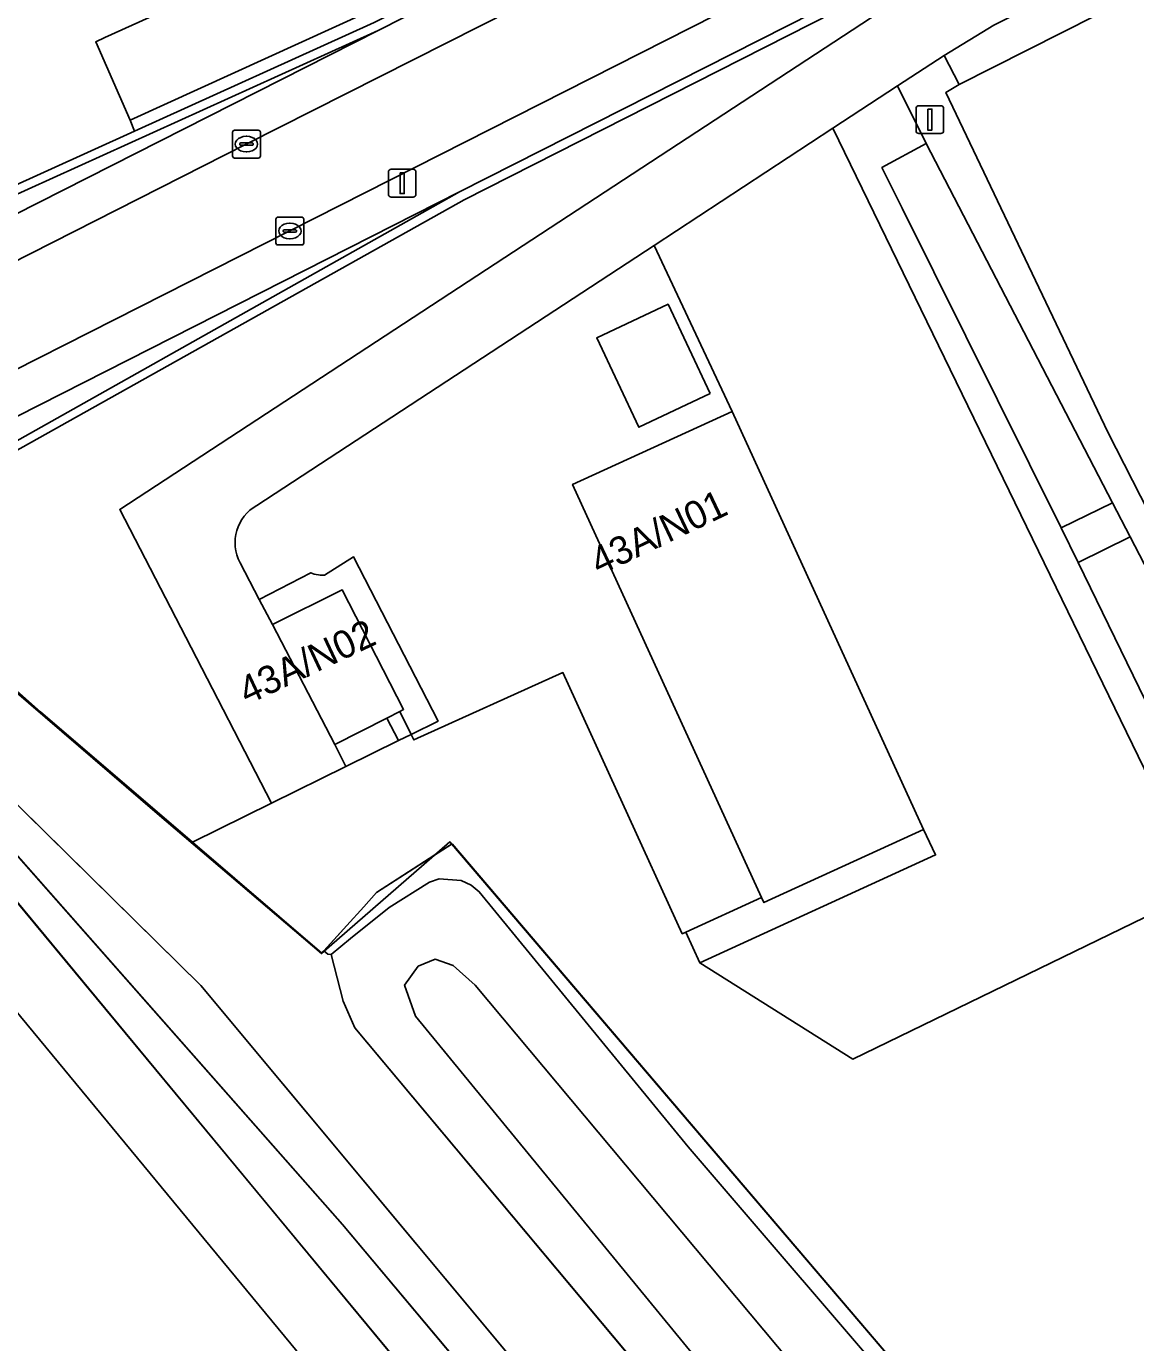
# Model space of a CAD drawing. Extents: x 157320 to 158835, y 386650 to 388491.
# Drawn here: x 157425.92 to 157465.77, y 387529.81 to 387577.08 of the extents above; entities that cross this region are included whole.
import ezdxf

# ---------------------------------------------------------------- set-up
doc = ezdxf.new("R2010")
doc.units = 0
for name, color, linetype in [('IMGEO_Berm_open', 7, 'Continuous'), ('IMGEO_Dek', 7, 'Continuous'), ('IMGEO_Erf', 7, 'Continuous'), ('IMGEO_Fietspad_gesloten', 7, 'Continuous'), ('IMGEO_Geluidsscherm', 7, 'Continuous'), ('IMGEO_Grasland_overig', 7, 'Continuous'), ('IMGEO_Groenvoorziening', 7, 'Continuous'), ('IMGEO_Hek', 7, 'Continuous'), ('IMGEO_Kolk', 7, 'Continuous'), ('IMGEO_Lichtmast', 7, 'Continuous'), ('IMGEO_Meer_plas_ven_vijver', 7, 'Continuous'), ('IMGEO_Muur', 7, 'Continuous'), ('IMGEO_Oever', 7, 'Continuous'), ('IMGEO_Pand', 7, 'Continuous'), ('IMGEO_Pand_nummerreeks', 7, 'Continuous'), ('IMGEO_Parkeervlak_open', 7, 'Continuous'), ('IMGEO_Rijbaan_lokaal_open', 7, 'Continuous'), ('IMGEO_Spoor', 7, 'Continuous'), ('IMGEO_Spoorbaan_halfverhard', 7, 'Continuous'), ('IMGEO_Voetpad_open', 7, 'Continuous'), ('IMGEO_Waterloop', 7, 'Continuous')]:
    doc.layers.add(name, color=color, linetype=linetype)

msp = doc.modelspace()

# ---------------------------------------------------------------- linework, layer by layer
at = {"layer": 'IMGEO_Berm_open'}
for points in [[(157470.771, 387593.59), (157470.568, 387593.961), (157468.366, 387592.876), (157467.91, 387592.639), (157452.596, 387584.902), (157438.44, 387577.734), (157438.25, 387577.629), (157429.654, 387573.707), (157429.806, 387573.314), (157438.415, 387577.215)], [(157438.555, 387576.929), (157414.303, 387565.939), (157415.05, 387565.021)], [(157441.48, 387571.141), (157419.244, 387559.866), (157419.925, 387559.029)]]:
    msp.add_lwpolyline(points, close=True, dxfattribs=at)
at = {"layer": 'IMGEO_Dek'}
msp.add_lwpolyline([(157463.092, 387559.076), (157463.702, 387557.826), (157465.573, 387558.748), (157464.941, 387559.968)], close=True, dxfattribs=at)
at = {"layer": 'IMGEO_Erf'}
for points in [[(157414.095, 387566.194), (157429.806, 387573.314), (157429.654, 387573.707), (157428.415, 387576.527), (157428.741, 387576.675), (157434.392, 387579.243), (157433.897, 387580.178), (157436.414, 387581.319), (157439.973, 387583.126), (157444.069, 387585.194), (157444.6, 387585.462), (157468.188, 387597.53), (157456.697, 387614.284)], [(157445.197, 387553.877), (157449.484, 387544.495), (157449.612, 387544.553), (157452.333, 387545.796), (157445.544, 387560.633), (157451.273, 387563.255), (157448.47, 387569.217), (157434.202, 387559.877)], [(157433.601, 387557.819), (157434.292, 387556.505), (157436.148, 387557.459), (157436.265, 387557.415), (157436.488, 387557.372), (157436.637, 387557.369), (157437.678, 387558.031), (157440.715, 387552.135), (157439.747, 387551.657), (157439.845, 387551.46), (157445.197, 387553.877)]]:
    msp.add_lwpolyline(points, dxfattribs=at)
for points in [[(157489.504, 387580.154), (157485.892, 387588.103), (157485.789, 387588.051), (157485.69, 387588.242), (157478.875, 387584.813), (157476.738, 387583.733), (157476.239, 387583.497), (157475.415, 387583.071), (157459.432, 387574.995), (157458.953, 387574.71), (157464.773, 387562.506), (157473.594, 387545.224), (157492.088, 387553.929), (157499.149, 387557.253), (157498.521, 387559.147)], [(157450.489, 387563.891), (157447.928, 387562.682), (157446.413, 387565.891), (157448.973, 387567.1)]]:
    msp.add_lwpolyline(points, close=True, dxfattribs=at)
msp.add_arc((157434.947, 387558.543), 1.528, 119.1728, 208.2683, dxfattribs=at)
at = {"layer": 'IMGEO_Fietspad_gesloten'}
msp.add_lwpolyline([(157418.265, 387561.069), (157435.385, 387569.732), (157456.986, 387580.686), (157473.14, 387588.869), (157472.349, 387590.404), (157471.557, 387591.939), (157455.422, 387583.768), (157433.825, 387572.851), (157416.027, 387563.82)], close=True, dxfattribs=at)
at = {"layer": 'IMGEO_Geluidsscherm'}
msp.add_lwpolyline([(157415.929, 387557.315), (157425.299, 387545.998), (157482.487, 387476.867)], dxfattribs=at)
at = {"layer": 'IMGEO_Grasland_overig'}
for points in [[(157450.612, 387525.728), (157437.72, 387541.121), (157437.308, 387542.077), (157436.867, 387543.753), (157436.751, 387543.763), (157436.612, 387543.88), (157436.538, 387543.798), (157431.889, 387547.783), (157426.43, 387552.461), (157422.278, 387556.137), (157420.115, 387558.795), (157419.925, 387559.029), (157419.244, 387559.866), (157418.265, 387561.069), (157416.027, 387563.82), (157415.05, 387565.021), (157414.303, 387565.939), (157414.171, 387565.747), (157410.526, 387563.868), (157410.618, 387563.756), (157416.342, 387556.778), (157418.275, 387554.423), (157465.975, 387496.899)], [(157449.562, 387519.43), (157437.279, 387534.06), (157418.932, 387554.849), (157419.487, 387555.301), (157421.955, 387552.709), (157432.187, 387542.644), (157461.467, 387507.547)], [(157951.797, 386913.771), (157861.897, 387021.979), (157796.633, 387101.231), (157746.598, 387161.798), (157682.888, 387239.101), (157624.888, 387309.155), (157593.061, 387348.178), (157583.647, 387359.861), (157556.841, 387392.276), (157497.657, 387463.56), (157461.467, 387507.547), (157432.187, 387542.644), (157421.955, 387552.709), (157419.487, 387555.301), (157418.932, 387554.849), (157437.279, 387534.06), (157449.562, 387519.43), (157475.314, 387488.447), (157486.059, 387475.384), (157545.298, 387403.37), (157576.983, 387365.251), (157604.978, 387331.198), (157733.746, 387175.562), (157897.258, 386977.614)]]:
    msp.add_lwpolyline(points, dxfattribs=at)
msp.add_lwpolyline([(157437.435, 387544.795), (157436.612, 387543.88), (157436.751, 387543.763), (157436.867, 387543.753), (157437.565, 387544.323), (157438.952, 387545.443), (157440.409, 387546.351), (157440.756, 387546.465), (157441.541, 387546.406), (157441.903, 387546.246), (157442.194, 387546.006), (157449.701, 387536.843), (157482.287, 387498.843), (157503.88, 387473.398), (157581.378, 387381.106), (157581.232, 387383.779), (157535.591, 387437.194), (157477.627, 387505.031), (157476.381, 387506.491), (157441.215, 387547.725), (157440.971, 387547.568), (157438.495, 387545.973), (157438.04, 387545.467)], close=True, dxfattribs=at)
at = {"layer": 'IMGEO_Groenvoorziening'}
for points in [[(157429.276, 387559.732), (157458.882, 387579.113), (157459.1, 387579.229), (157459.289, 387579.324), (157459.097, 387579.703), (157441.648, 387570.849), (157420.115, 387558.795), (157422.278, 387556.137), (157426.43, 387552.461), (157431.889, 387547.783), (157434.731, 387549.184), (157431.648, 387555.145)], [(157450.114, 387543.452), (157455.611, 387539.998), (157468.179, 387546.099), (157454.897, 387573.424), (157448.47, 387569.217), (157451.273, 387563.255), (157458.143, 387548.24), (157458.58, 387547.328)]]:
    msp.add_lwpolyline(points, close=True, dxfattribs=at)
for points in [[(157473.594, 387545.224), (157464.773, 387562.506), (157458.953, 387574.71), (157459.432, 387574.995), (157458.887, 387576.036), (157457.215, 387574.942), (157458.246, 387572.872), (157464.941, 387559.968), (157465.573, 387558.748), (157473.392, 387543.678)], [(157470.495, 387543.879), (157463.702, 387557.826), (157463.092, 387559.076), (157457.38, 387570.552), (157456.654, 387572.01), (157458.246, 387572.872), (157457.215, 387574.942), (157454.897, 387573.424), (157468.179, 387546.099), (157455.611, 387539.998), (157450.114, 387543.452), (157449.612, 387544.553), (157449.484, 387544.495), (157445.197, 387553.877), (157439.845, 387551.46), (157439.747, 387551.657), (157439.294, 387551.434), (157437.4, 387550.497), (157434.731, 387549.184), (157431.889, 387547.783), (157436.538, 387543.798), (157436.612, 387543.88), (157437.435, 387544.795), (157438.04, 387545.467), (157438.495, 387545.973), (157440.971, 387547.568), (157441.215, 387547.725), (157476.381, 387506.491)]]:
    msp.add_lwpolyline(points, dxfattribs=at)
at = {"layer": 'IMGEO_Hek'}
for points in [[(157459.432, 387574.995), (157458.953, 387574.71), (157464.773, 387562.506)], [(157451.273, 387563.255), (157448.47, 387569.217)], [(157464.773, 387562.506), (157473.594, 387545.224)], [(157507.599, 387469.915), (157500.495, 387478.172), (157494.637, 387485.058), (157481.256, 387500.77), (157471.008, 387512.799), (157441.135, 387547.797), (157436.521, 387543.782), (157430.627, 387548.82), (157424.871, 387553.742), (157422.682, 387554.977), (157419.535, 387558.788)], [(157426.43, 387552.461), (157422.278, 387556.137)], [(157439.747, 387551.657), (157439.845, 387551.46), (157445.197, 387553.877), (157449.484, 387544.495), (157449.612, 387544.553)], [(157431.889, 387547.783), (157426.43, 387552.461)], [(157439.335, 387552.481), (157439.747, 387551.657)], [(157437.435, 387544.795), (157436.538, 387543.798), (157431.889, 387547.783)], [(157438.04, 387545.467), (157438.495, 387545.973), (157441.215, 387547.725), (157476.381, 387506.491)], [(157449.612, 387544.553), (157452.333, 387545.796)], [(157438.04, 387545.467), (157437.435, 387544.795)]]:
    msp.add_lwpolyline(points, dxfattribs=at)
at = {"layer": 'IMGEO_Kolk'}
for p, q in [((157433.328, 387572.426), (157433.328, 387573.278)), ((157433.403, 387573.352), (157434.255, 387573.352)), ((157433.816, 387573.132), (157433.841, 387573.132)), ((157434.329, 387573.278), (157434.329, 387572.426)), ((157433.587, 387572.846), (157433.587, 387572.858)), ((157434.025, 387572.809), (157433.627, 387572.809)), ((157433.63, 387572.895), (157434.028, 387572.895)), ((157433.839, 387572.572), (157433.814, 387572.572)), ((157434.071, 387572.858), (157434.071, 387572.846)), ((157434.255, 387572.352), (157433.403, 387572.352)), ((157434.964, 387570.231), (157435.816, 387570.231)), ((157434.889, 387569.305), (157434.889, 387570.157)), ((157435.148, 387569.725), (157435.148, 387569.737)), ((157435.191, 387569.774), (157435.589, 387569.774)), ((157435.377, 387570.011), (157435.402, 387570.011)), ((157435.632, 387569.737), (157435.632, 387569.725)), ((157435.89, 387570.157), (157435.89, 387569.305)), ((157435.816, 387569.231), (157434.964, 387569.231)), ((157435.586, 387569.688), (157435.188, 387569.688)), ((157435.4, 387569.451), (157435.375, 387569.451))]:
    msp.add_line(p, q, dxfattribs=at)
for points in [[(157433.328, 387572.426), (157433.328, 387573.278)], [(157433.403, 387573.352), (157434.255, 387573.352)], [(157434.329, 387573.278), (157434.329, 387572.426)], [(157434.255, 387572.352), (157433.403, 387572.352)], [(157434.964, 387570.231), (157435.816, 387570.231)], [(157434.889, 387569.305), (157434.889, 387570.157)], [(157435.89, 387570.157), (157435.89, 387569.305)], [(157435.816, 387569.231), (157434.964, 387569.231)]]:
    msp.add_lwpolyline(points, dxfattribs=at)
for centre, radius, start, end in [((157433.405, 387573.276), 0.0765, 91.552, 178.448), ((157433.405, 387573.276), 0.0765, 91.552, 178.448), ((157434.253, 387573.276), 0.0765, 1.552, 88.448), ((157434.253, 387573.276), 0.0765, 1.552, 88.448), ((157433.627, 387572.855), 0.0403, 85.8775, 175.7526), ((157433.624, 387572.845), 0.0366, 178.938, 274.7102), ((157434.028, 387572.852), 0.043, 264.8664, 352.4533), ((157434.032, 387572.857), 0.0386, 1.7309, 96.639), ((157433.405, 387572.428), 0.0765, 181.552, 268.448), ((157433.405, 387572.428), 0.0765, 181.552, 268.448), ((157434.253, 387572.428), 0.0765, 271.552, 358.448), ((157434.253, 387572.428), 0.0765, 271.552, 358.448), ((157434.966, 387570.155), 0.0765, 91.552, 178.448), ((157434.966, 387570.155), 0.0765, 91.552, 178.448), ((157435.814, 387570.155), 0.0765, 1.552, 88.448), ((157435.814, 387570.155), 0.0765, 1.552, 88.448), ((157435.188, 387569.734), 0.0403, 85.8775, 175.7526), ((157435.185, 387569.724), 0.0366, 178.938, 274.7102), ((157435.589, 387569.731), 0.043, 264.8664, 352.4533), ((157435.593, 387569.736), 0.0386, 1.7309, 96.639), ((157434.966, 387569.307), 0.0765, 181.552, 268.448), ((157434.966, 387569.307), 0.0765, 181.552, 268.448), ((157435.814, 387569.307), 0.0765, 271.552, 358.448), ((157435.814, 387569.307), 0.0765, 271.552, 358.448)]:
    msp.add_arc(centre, radius, start, end, dxfattribs=at)
for centre, major_axis, ratio, start_param, end_param in [((157433.815, 387572.852), (-0.387, 0.002), 0.722429, 4.712389, 7.853982), ((157433.84, 387572.852), (-0.39, 0.002), 0.717154, 1.570796, 4.712389), ((157435.376, 387569.731), (-0.387, 0.002), 0.722429, 4.712389, 7.853982), ((157435.401, 387569.731), (-0.39, 0.002), 0.717154, 1.570796, 4.712389)]:
    msp.add_ellipse(centre, major_axis=major_axis, ratio=ratio, start_param=start_param, end_param=end_param, dxfattribs=at)
at = {"layer": 'IMGEO_Lichtmast'}
for p, q in [((157457.882, 387573.332), (157457.882, 387574.132)), ((157457.882, 387574.132), (157457.882, 387573.332)), ((157457.982, 387574.232), (157458.772, 387574.232)), ((157458.772, 387574.232), (157457.982, 387574.232)), ((157458.872, 387574.132), (157458.872, 387573.332)), ((157458.872, 387573.332), (157458.872, 387574.132)), ((157458.772, 387573.232), (157457.982, 387573.232)), ((157457.982, 387573.232), (157458.772, 387573.232)), ((157438.929, 387571.051), (157438.929, 387571.851)), ((157438.929, 387571.851), (157438.929, 387571.051)), ((157439.029, 387571.951), (157439.819, 387571.951)), ((157439.819, 387571.951), (157439.029, 387571.951)), ((157439.919, 387571.851), (157439.919, 387571.051)), ((157439.919, 387571.051), (157439.919, 387571.851)), ((157439.819, 387570.951), (157439.029, 387570.951)), ((157439.029, 387570.951), (157439.819, 387570.951))]:
    msp.add_line(p, q, dxfattribs=at)
for points in [[(157458.302, 387574.107), (157458.452, 387574.107), (157458.452, 387573.357), (157458.302, 387573.357), (157458.302, 387574.107)], [(157439.349, 387571.826), (157439.499, 387571.826), (157439.499, 387571.076), (157439.349, 387571.076), (157439.349, 387571.826)]]:
    msp.add_lwpolyline(points, dxfattribs=at)
for centre, start, end in [((157457.982, 387574.132), 90, 180), ((157457.982, 387574.132), 90, 180), ((157458.772, 387574.132), 0, 90), ((157458.772, 387574.132), 360, 90), ((157457.982, 387573.332), 180, 270), ((157457.982, 387573.332), 180, 270), ((157458.772, 387573.332), 270, 0), ((157458.772, 387573.332), 270, 0), ((157439.029, 387571.851), 90, 180), ((157439.029, 387571.851), 90, 180), ((157439.819, 387571.851), 0, 90), ((157439.819, 387571.851), 360, 90), ((157439.029, 387571.051), 180, 270), ((157439.029, 387571.051), 180, 270), ((157439.819, 387571.051), 270, 0), ((157439.819, 387571.051), 270, 0)]:
    msp.add_arc(centre, 0.1, start, end, dxfattribs=at)
at = {"layer": 'IMGEO_Meer_plas_ven_vijver'}
msp.add_lwpolyline([(157465.573, 387558.748), (157464.941, 387559.968), (157458.246, 387572.872), (157456.654, 387572.01), (157457.38, 387570.552), (157463.092, 387559.076), (157463.702, 387557.826), (157470.495, 387543.879), (157473.392, 387543.678)], close=True, dxfattribs=at)
at = {"layer": 'IMGEO_Muur'}
for points in [[(157438.555, 387576.929), (157470.913, 387593.326), (157470.771, 387593.59), (157438.415, 387577.215), (157429.806, 387573.314), (157414.095, 387566.194), (157414.303, 387565.939)], [(157473.956, 387587.242), (157473.819, 387587.515), (157441.48, 387571.141), (157419.925, 387559.029), (157420.115, 387558.795), (157441.648, 387570.849), (157459.097, 387579.703)]]:
    msp.add_lwpolyline(points, close=True, dxfattribs=at)
at = {"layer": 'IMGEO_Oever'}
for points in [[(157726.104, 387204.716), (157724.821, 387202.799), (157721.371, 387208.687), (157716.262, 387215.133), (157674.133, 387267.019), (157671.492, 387270.213), (157581.387, 387381.095), (157581.378, 387381.106), (157503.88, 387473.398), (157482.287, 387498.843), (157449.701, 387536.843), (157442.194, 387546.006), (157441.903, 387546.246), (157441.541, 387546.406), (157440.756, 387546.465), (157440.409, 387546.351), (157438.952, 387545.443), (157437.565, 387544.323), (157436.867, 387543.753)], [(157436.867, 387543.753), (157437.308, 387542.077), (157437.72, 387541.121), (157450.612, 387525.728), (157472.211, 387499.437), (157493.829, 387473.484), (157521.957, 387439.689), (157542.93, 387414.951), (157572.69, 387378.488), (157623.838, 387316.657), (157655.205, 387278.319), (157677.296, 387251.894), (157695.306, 387230.058), (157707.9, 387214.963), (157722.926, 387196.42), (157743.703, 387171.28), (157757.999, 387153.802), (157775.496, 387132.855), (157786.688, 387119.266), (157803.439, 387099.178), (157815.719, 387084), (157833.677, 387062.453)], [(157603.757, 387343.057), (157595.038, 387353.812), (157569.621, 387384.62), (157544.833, 387414.91), (157513.198, 387452.572), (157480.328, 387492.278), (157439.901, 387541.542), (157439.507, 387542.655), (157440, 387543.332), (157440.604, 387543.59), (157441.251, 387543.351), (157442.045, 387542.651), (157455.353, 387526.745), (157484.156, 387491.769), (157514.112, 387454.819), (157531.631, 387434.104), (157554.086, 387406.464), (157577.288, 387379.121), (157590.443, 387363.191), (157611.569, 387337.287)]]:
    msp.add_lwpolyline(points, dxfattribs=at)
at = {"layer": 'IMGEO_Pand'}
for points in [[(157450.489, 387563.891), (157448.973, 387567.1), (157446.413, 387565.891), (157447.928, 387562.682)], [(157458.143, 387548.24), (157451.273, 387563.255), (157445.544, 387560.633), (157452.333, 387545.796), (157452.414, 387545.619)], [(157439.335, 387552.481), (157439.472, 387552.551), (157437.262, 387556.849), (157434.768, 387555.6), (157436.999, 387551.29), (157438.868, 387552.243)]]:
    msp.add_lwpolyline(points, close=True, dxfattribs=at)
at = {"layer": 'IMGEO_Parkeervlak_open'}
msp.add_lwpolyline([(157459.432, 387574.995), (157475.415, 387583.071), (157476.239, 387583.497), (157476.738, 387583.733), (157475.174, 387584.46), (157460.674, 387577.122), (157458.887, 387576.036)], close=True, dxfattribs=at)
at = {"layer": 'IMGEO_Rijbaan_lokaal_open'}
msp.add_lwpolyline([(157429.654, 387573.707), (157438.25, 387577.629), (157438.44, 387577.734), (157452.596, 387584.902), (157467.91, 387592.639), (157468.366, 387592.876), (157466.982, 387595.618), (157445.088, 387584.519), (157440.46, 387582.17), (157436.923, 387580.393), (157434.392, 387579.243), (157428.741, 387576.675), (157428.415, 387576.527)], close=True, dxfattribs=at)
msp.add_lwpolyline([(157434.202, 387559.877), (157448.47, 387569.217), (157454.897, 387573.424), (157457.215, 387574.942), (157458.887, 387576.036), (157460.674, 387577.122), (157475.174, 387584.46), (157472.185, 387585.84), (157472.011, 387585.753), (157467.056, 387583.235), (157463.083, 387581.233), (157459.289, 387579.324), (157459.1, 387579.229), (157458.882, 387579.113), (157429.276, 387559.732), (157431.648, 387555.145), (157434.731, 387549.184), (157437.4, 387550.497), (157436.999, 387551.29), (157434.768, 387555.6), (157434.292, 387556.505), (157433.601, 387557.819)], dxfattribs=at)
msp.add_arc((157434.947, 387558.543), 1.528, 119.1728, 208.2683, dxfattribs=at)
at = {"layer": 'IMGEO_Spoor'}
msp.add_lwpolyline([(157408.215, 387562.677), (157414.058, 387555.61), (157571.705, 387364.958), (157581.654, 387352.629), (157671.587, 387243.978), (157730.397, 387172.631), (157983.728, 386866.099), (158139.862, 386676.991)], dxfattribs=at)
at = {"layer": 'IMGEO_Spoorbaan_halfverhard'}
msp.add_lwpolyline([(157604.978, 387331.198), (157576.983, 387365.251), (157545.298, 387403.37), (157486.059, 387475.384), (157484.628, 387474.184), (157465.975, 387496.899), (157418.275, 387554.423), (157416.342, 387556.778), (157410.618, 387563.756), (157410.526, 387563.868), (157408.411, 387566.446), (157387.799, 387591.57), (157369.961, 387612.94), (157371.479, 387614.245), (157345.109, 387646.08), (157319.732, 387630.105), (157340.02, 387605.692), (157387.764, 387548.827), (157437.896, 387489.118), (157499.003, 387416.961), (157530.685, 387379.55), (157602.326, 387293.743)], dxfattribs=at)
at = {"layer": 'IMGEO_Voetpad_open'}
for points in [[(157416.027, 387563.82), (157433.825, 387572.851), (157455.422, 387583.768), (157471.557, 387591.939), (157470.913, 387593.326), (157438.555, 387576.929), (157415.05, 387565.021)], [(157419.244, 387559.866), (157441.48, 387571.141), (157473.819, 387587.515), (157473.14, 387588.869), (157456.986, 387580.686), (157435.385, 387569.732), (157418.265, 387561.069)], [(157465.573, 387558.748), (157464.941, 387559.968), (157463.092, 387559.076), (157463.702, 387557.826)], [(157439.335, 387552.481), (157439.747, 387551.657), (157440.715, 387552.135), (157437.678, 387558.031), (157436.637, 387557.369), (157436.488, 387557.372), (157436.265, 387557.415), (157436.148, 387557.459), (157434.292, 387556.505), (157434.768, 387555.6), (157437.262, 387556.849), (157439.472, 387552.551)], [(157438.868, 387552.243), (157436.999, 387551.29), (157437.4, 387550.497), (157439.294, 387551.434)], [(157438.868, 387552.243), (157439.294, 387551.434), (157439.747, 387551.657), (157439.335, 387552.481)], [(157458.58, 387547.328), (157458.143, 387548.24), (157452.414, 387545.619), (157452.333, 387545.796), (157449.612, 387544.553), (157450.114, 387543.452)]]:
    msp.add_lwpolyline(points, close=True, dxfattribs=at)
at = {"layer": 'IMGEO_Waterloop'}
msp.add_lwpolyline([(157611.569, 387337.287), (157590.443, 387363.191), (157577.288, 387379.121), (157554.086, 387406.464), (157531.631, 387434.104), (157514.112, 387454.819), (157484.156, 387491.769), (157455.353, 387526.745), (157442.045, 387542.651), (157441.251, 387543.351), (157440.604, 387543.59), (157440, 387543.332), (157439.507, 387542.655), (157439.901, 387541.542), (157480.328, 387492.278), (157513.198, 387452.572), (157544.833, 387414.91), (157569.621, 387384.62), (157595.038, 387353.812), (157603.757, 387343.057)], dxfattribs=at)

# ---------------------------------------------------------------- texts
at = {"layer": 'IMGEO_Pand_nummerreeks'}
for s, rotation, p in [('43A/N01', 25.3763, (157446.49, 387557.348)), ('43A/N02', 25.1987, (157433.854, 387552.705))]:
    msp.add_text(s, height=1, rotation=rotation, dxfattribs=at).set_placement(p)

doc.saveas('drawing.dxf')
